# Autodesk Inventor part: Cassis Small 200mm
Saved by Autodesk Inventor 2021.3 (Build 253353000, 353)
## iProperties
Created: 2023-09
Part Number: Cassis Small 200mm
Material: Generic
Document SubType Name: Modeling
Designer: AdminForWorker
Density: 1 g/cm^3
Appearance: Default
Title: Cassis Small 200mm v2
Author: AdminForWorker
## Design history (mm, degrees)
feature "Body1"
feature "Body2"
feature "Body3"
feature "Body4"
feature "Body5"
feature "Body6"
body "Solid1"
body "Solid2"
body "Solid3"
body "Solid4"
body "Solid5"
body "Solid6"
